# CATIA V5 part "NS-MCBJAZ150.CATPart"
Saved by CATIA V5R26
Part number: NS-MCBJAZ150
Bounding box of the stored display mesh (mm): x -60 to 120, y 0 to 198, z -60 to 60
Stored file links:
  R:\Document\坂尻\その他\ナベヤデータ変換\安全カバーキャスター\MCBJSAZ150\NS-MCBJAZ150.CATPart
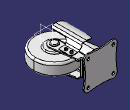
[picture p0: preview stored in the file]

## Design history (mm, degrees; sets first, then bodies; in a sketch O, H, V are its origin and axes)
Body1 (main body)
  Solid1: solid without history
  Body2
    Solid2: solid without history
  Assemble1: tool Body2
